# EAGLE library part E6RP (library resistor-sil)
SIL RESISTOR
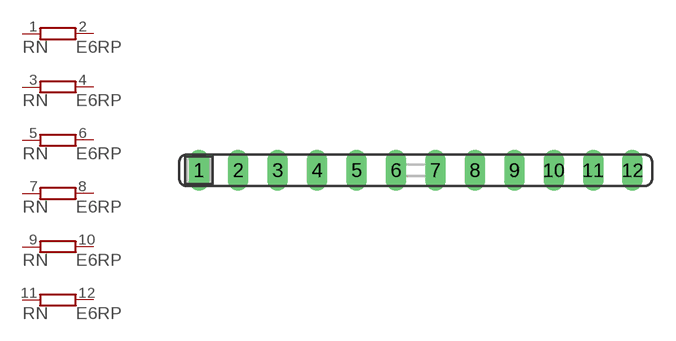
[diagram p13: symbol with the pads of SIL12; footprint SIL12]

Designator prefix RN; gates A=RPV B=RPV C=RPV D=RPV E=RPV F=RPV

## E6RP (OC_FARNELL: unknown; OC_NEWARK: unknown)  [SIL12]
1  A:1  pas
2  A:2  pas
3  B:1  pas
4  B:2  pas
5  C:1  pas
6  C:2  pas
7  D:1  pas
8  D:2  pas
9  E:1  pas
10  E:2  pas
11  F:1  pas
12  F:2  pas

## Footprint SIL12 (pad centres in mm)
Single In Line
drill 0.813 long: 1 -13.97,0; 2 -11.43,0; 3 -8.89,0; 4 -6.35,0; 5 -3.81,0; 6 -1.27,0; 7 1.27,0; 8 3.81,0; 9 6.35,0; 10 8.89,0; 11 11.43,0; 12 13.97,0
